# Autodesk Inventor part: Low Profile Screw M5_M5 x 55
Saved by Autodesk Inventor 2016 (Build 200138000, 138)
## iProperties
Created: 2015-11
Part Number: Low Profile Screw M5_M5 x 55
Material: Generic
Document SubType Name: Modeling
Designer: John
Density: 1 g/cm^3
Appearance: Default
Author: John
Revision Number: ANY
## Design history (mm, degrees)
feature "Cut-Extrude2"
body "Solid1"
